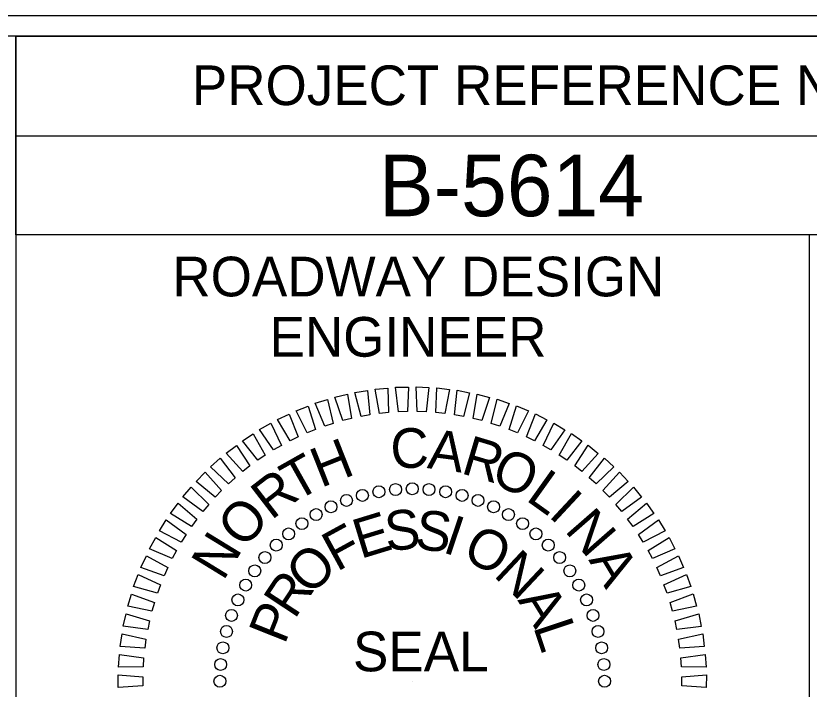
# Model space of a CAD drawing. Extents: x 1633303 to 1635397, y 883210 to 885302.
# Drawn here: x 1635163.8 to 1635263.8, y 884890.3 to 884975.2 of the extents above; entities that cross this region are included whole.
import ezdxf

# ---------------------------------------------------------------- set-up
doc = ezdxf.new("R2010")
doc.units = 0
for name, color, linetype in [('Sheet Data Field CELL', 7, 'Continuous'), ('Sheet PE Seal Cell', 7, 'Continuous'), ('Sheet Plan And Profile CELL', 7, 'Continuous'), ('Sheet Plot Border Inside CELL', 7, 'Continuous'), ('Sheet Profile CELL', 7, 'Continuous'), ('Sheet Profile Grid Major CELL', 7, 'Continuous')]:
    doc.layers.add(name, color=color, linetype=linetype)

msp = doc.modelspace()

# ---------------------------------------------------------------- linework, layer by layer
at = {"layer": 'Sheet PE Seal Cell'}
msp.add_line((1635213.8, 884891.31), (1635213.8, 884891.31), dxfattribs=at)
for points in [[(1635207.34, 884924.68), (1635206.56, 884927.7), (1635208.16, 884927.95), (1635208.46, 884924.88)], [(1635209.68, 884925.05), (1635209.12, 884928.12), (1635210.73, 884928.26), (1635210.82, 884925.17)], [(1635212.05, 884925.25), (1635211.7, 884928.35), (1635213.32, 884928.38), (1635213.19, 884925.3)], [(1635214.42, 884925.29), (1635214.29, 884928.41), (1635215.9, 884928.33), (1635215.56, 884925.26)], [(1635216.79, 884925.17), (1635216.88, 884928.29), (1635218.48, 884928.09), (1635217.92, 884925.06)], [(1635219.14, 884924.88), (1635219.45, 884927.98), (1635221.03, 884927.67), (1635220.27, 884924.69)], [(1635202.76, 884923.45), (1635201.57, 884926.34), (1635203.12, 884926.81), (1635203.84, 884923.81)], [(1635205.03, 884924.15), (1635204.04, 884927.11), (1635205.62, 884927.47), (1635206.13, 884924.43)], [(1635221.47, 884924.42), (1635221.99, 884927.5), (1635223.55, 884927.08), (1635222.58, 884924.15)], [(1635223.76, 884923.81), (1635224.5, 884926.84), (1635226.03, 884926.31), (1635224.85, 884923.46)], [(1635200.54, 884922.61), (1635199.16, 884925.4), (1635200.66, 884925.98), (1635201.6, 884923.04)], [(1635226, 884923.03), (1635226.95, 884926.01), (1635228.44, 884925.37), (1635227.07, 884922.61)], [(1635198.39, 884921.6), (1635196.81, 884924.3), (1635198.28, 884924.98), (1635199.41, 884922.11)], [(1635228.19, 884922.1), (1635229.34, 884925), (1635230.78, 884924.27), (1635229.22, 884921.61)], [(1635196.31, 884920.46), (1635194.55, 884923.03), (1635195.97, 884923.82), (1635197.3, 884921.03)], [(1635230.3, 884921.03), (1635231.65, 884923.84), (1635233.04, 884923.01), (1635231.29, 884920.46)], [(1635194.32, 884919.16), (1635192.39, 884921.61), (1635193.74, 884922.49), (1635195.27, 884919.81)], [(1635232.33, 884919.8), (1635233.88, 884922.51), (1635235.2, 884921.59), (1635233.28, 884919.17)], [(1635192.43, 884917.74), (1635190.33, 884920.04), (1635191.62, 884921.02), (1635193.32, 884918.45)], [(1635234.28, 884918.44), (1635236, 884921.04), (1635237.26, 884920.02), (1635235.18, 884917.74)], [(1635190.64, 884916.18), (1635188.38, 884918.34), (1635189.6, 884919.4), (1635191.48, 884916.95)], [(1635236.12, 884916.95), (1635238.02, 884919.42), (1635239.21, 884918.31), (1635236.97, 884916.19)], [(1635188.96, 884914.51), (1635186.55, 884916.5), (1635187.7, 884917.64), (1635189.75, 884915.33)], [(1635237.85, 884915.33), (1635239.93, 884917.66), (1635241.03, 884916.48), (1635238.65, 884914.51)], [(1635187.4, 884912.72), (1635184.86, 884914.54), (1635185.92, 884915.76), (1635188.13, 884913.6)], [(1635239.47, 884913.59), (1635241.7, 884915.77), (1635242.72, 884914.52), (1635240.21, 884912.72)], [(1635185.97, 884910.82), (1635183.31, 884912.46), (1635184.29, 884913.75), (1635186.64, 884911.75)], [(1635240.96, 884911.75), (1635243.34, 884913.77), (1635244.27, 884912.44), (1635241.64, 884910.83)], [(1635184.68, 884908.83), (1635181.91, 884910.28), (1635182.79, 884911.64), (1635185.28, 884909.81)], [(1635242.32, 884909.8), (1635244.83, 884911.65), (1635245.67, 884910.27), (1635242.93, 884908.84)], [(1635183.53, 884906.76), (1635180.67, 884908.01), (1635181.45, 884909.43), (1635184.06, 884907.77)], [(1635243.54, 884907.77), (1635246.18, 884909.44), (1635246.91, 884908), (1635244.08, 884906.76)], [(1635182.52, 884904.61), (1635179.58, 884905.66), (1635180.27, 884907.12), (1635182.98, 884905.66)], [(1635244.62, 884905.65), (1635247.36, 884907.13), (1635247.99, 884905.65), (1635245.09, 884904.61)], [(1635181.67, 884902.4), (1635178.66, 884903.24), (1635179.24, 884904.75), (1635182.05, 884903.47)], [(1635245.54, 884903.47), (1635248.39, 884904.75), (1635248.91, 884903.23), (1635245.94, 884902.4)], [(1635180.97, 884900.13), (1635177.92, 884900.76), (1635178.39, 884902.3), (1635181.28, 884901.23)], [(1635246.31, 884901.22), (1635249.24, 884902.31), (1635249.66, 884900.75), (1635246.63, 884900.13)], [(1635180.44, 884897.82), (1635177.35, 884898.23), (1635177.71, 884899.81), (1635180.67, 884898.94)], [(1635246.93, 884898.93), (1635249.92, 884899.81), (1635250.23, 884898.22), (1635247.17, 884897.82)], [(1635180.07, 884895.47), (1635176.95, 884895.67), (1635177.21, 884897.27), (1635180.22, 884896.61)], [(1635247.38, 884896.6), (1635250.43, 884897.27), (1635250.62, 884895.67), (1635247.54, 884895.47)], [(1635179.86, 884893.11), (1635176.74, 884893.09), (1635176.88, 884894.7), (1635179.93, 884894.25)], [(1635247.66, 884894.25), (1635250.75, 884894.7), (1635250.84, 884893.09), (1635247.75, 884893.11)], [(1635179.81, 884890.74), (1635176.7, 884890.5), (1635176.73, 884892.12), (1635179.81, 884891.88)], [(1635247.79, 884891.88), (1635250.9, 884892.11), (1635250.87, 884890.5), (1635247.79, 884890.74)]]:
    msp.add_lwpolyline(points, close=True, dxfattribs=at)
for centre in [(1635209.59, 884915.19), (1635211.69, 884915.47), (1635213.8, 884915.56), (1635215.91, 884915.47), (1635218.01, 884915.19), (1635205.51, 884914.1), (1635207.52, 884914.73), (1635220.08, 884914.73), (1635222.09, 884914.1), (1635203.55, 884913.29), (1635224.05, 884913.29), (1635201.68, 884912.31), (1635225.93, 884912.31), (1635199.89, 884911.17), (1635227.71, 884911.17), (1635198.21, 884909.88), (1635229.39, 884909.88), (1635196.65, 884908.46), (1635230.95, 884908.46), (1635195.22, 884906.9), (1635232.38, 884906.9), (1635193.94, 884905.22), (1635233.67, 884905.22), (1635192.8, 884903.43), (1635234.8, 884903.43), (1635191.82, 884901.56), (1635235.78, 884901.56), (1635191.01, 884899.6), (1635236.59, 884899.6), (1635190.38, 884897.58), (1635237.22, 884897.58), (1635189.92, 884895.52), (1635237.68, 884895.52), (1635189.64, 884893.42), (1635237.96, 884893.42), (1635189.55, 884891.31), (1635238.05, 884891.31)]:
    msp.add_circle(centre, 0.75, dxfattribs=at)
at = {"layer": 'Sheet Plan And Profile CELL'}
msp.add_line((1635263.84, 884947.56), (1635263.84, 884835.06), dxfattribs=at)
at = {"layer": 'Sheet Plot Border Inside CELL'}
msp.add_lwpolyline([(1635376.36, 884975.16), (1633709.86, 884975.16), (1633709.86, 883920.06), (1635376.36, 883920.06)], close=True, dxfattribs=at)
at = {"layer": 'Sheet Profile CELL'}
msp.add_line((1635163.81, 884960.06), (1635363.86, 884960.06), dxfattribs=at)
for points in [[(1635363.86, 884972.61), (1633863.86, 884972.61), (1633863.86, 883922.61), (1635363.86, 883922.61)], [(1635163.81, 884972.61), (1635363.86, 884972.61), (1635363.86, 884947.56), (1635163.81, 884947.56)]]:
    msp.add_lwpolyline(points, close=True, dxfattribs=at)
at = {"layer": 'Sheet Profile Grid Major CELL'}
msp.add_lwpolyline([(1635163.86, 883947.61), (1635163.86, 884972.61), (1635190.16, 884972.61)], dxfattribs=at)

# ---------------------------------------------------------------- texts
at = {"layer": 'Sheet Data Field CELL'}
msp.add_text('B-5614', height=7.75, dxfattribs=at).set_placement((1635209.59, 884949.91))
at = {"layer": 'Sheet PE Seal Cell'}
for s, rotation, p in [('C', 1.9618, (1635211.13, 884918.11)), ('A', 352.4568, (1635215.59, 884918.18)), ('H', 21.601, (1635202.28, 884915.65)), ('R', 343.4093, (1635219.8, 884917.56)), ('T', 29.3903, (1635199.09, 884913.87)), ('O', 335.2006, (1635223.48, 884916.44)), ('R', 37.5989, (1635196.02, 884911.53)), ('L', 324.4755, (1635227.99, 884914.2)), ('I', 317.0103, (1635230.85, 884912.16)), ('O', 48.3241, (1635192.56, 884907.87)), ('E', 16.986, (1635207.27, 884906.7)), ('S', 5.2237, (1635210.54, 884907.7)), ('S', 353.2648, (1635214.01, 884908.02)), ('N', 311.0704, (1635232.91, 884910.28)), ('I', 341.3058, (1635217.47, 884907.62)), ('F', 28.6639, (1635204.29, 884905.06)), ('O', 332.5504, (1635219.91, 884906.87)), ('N', 58.5345, (1635189.96, 884903.84)), ('O', 44.4727, (1635200.9, 884901.95)), ('N', 316.7416, (1635223.92, 884904.61)), ('A', 300.8599, (1635235.97, 884906.6)), ('R', 56.5721, (1635198.96, 884899.01)), ('A', 301.6915, (1635227.03, 884901.53)), ('P', 68.3344, (1635197.7, 884895.82)), ('L', 288.3556, (1635229.03, 884898.2)), ('SEAL', 360, (1635206.33, 884892.56))]:
    msp.add_text(s, height=5, rotation=rotation, dxfattribs=at).set_placement(p)
at = {"layer": 'Sheet Profile CELL'}
for s, height, p in [('PROJECT REFERENCE NO.', 5.0001, (1635186.01, 884963.91)), ('ROADWAY DESIGN', 5.0001, (1635183.55, 884939.81)), ('ENGINEER', 5, (1635195.8, 884932.21))]:
    msp.add_text(s, height=height, dxfattribs=at).set_placement(p)

doc.saveas('drawing.dxf')
